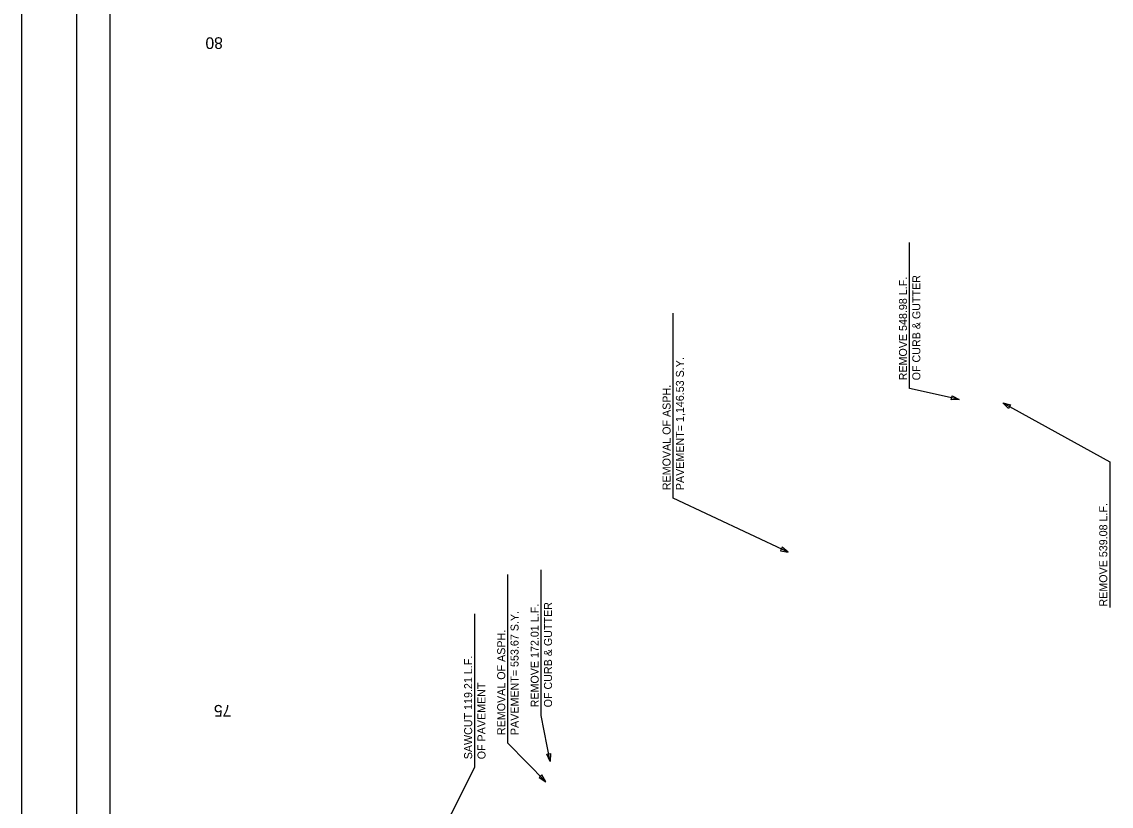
# Model space of a CAD drawing. Extents: x 2150645 to 2152288, y 141590 to 143592.
# Drawn here: x 2150645 to 2151462, y 142447 to 143034 of the extents above; entities that cross this region are included whole.
import ezdxf

# ---------------------------------------------------------------- set-up
doc = ezdxf.new("R2010")
doc.units = 0
for name, color, linetype in [('EX_Align', 7, 'Continuous'), ('EX_Align_Sta', 7, 'Continuous'), ('PR_Align_Ramp_D', 7, 'Continuous'), ('TOPO_DRAIN_Headwall', 7, 'Continuous'), ('TOPO_San Manhole', 7, 'Continuous')]:
    doc.layers.add(name, color=color, linetype=linetype)

msp = doc.modelspace()

# ---------------------------------------------------------------- linework, layer by layer
at = {"layer": 'EX_Align'}
msp.add_lwpolyline([(2150645.33, 141792.07), (2150645.33, 143592.07), (2151845.33, 143592.07), (2151845.33, 141792.07)], close=True, dxfattribs=at)
at = {"layer": 'PR_Align_Ramp_D'}
msp.add_lwpolyline([(2151761.58, 143546.45), (2151761.58, 141971.45), (2150711.58, 141971.45), (2150711.58, 143546.45)], close=True, dxfattribs=at)
at = {"layer": 'TOPO_DRAIN_Headwall'}
msp.add_lwpolyline([(2150686.58, 141873.95), (2150686.58, 143573.95), (2151786.58, 143573.95), (2151786.58, 141873.95)], close=True, dxfattribs=at)
at = {"layer": 'TOPO_San Manhole'}
for p, q in [((2151310.92, 142765.7), (2151310.92, 142868.89)), ((2151133.68, 142683.41), (2151133.68, 142816.16)), ((2151461.05, 142698.6), (2151461.05, 142595.42)), ((2151009.73, 142499.86), (2151009.73, 142620.17)), ((2151034.8, 142520.63), (2151034.8, 142623.82)), ((2150984.94, 142481.73), (2150984.94, 142590.81))]:
    msp.add_line(p, q, dxfattribs=at)
for points in [[(2151348.05, 142751.27), (2151310.92, 142759.7), (2151310.92, 142765.7)], [(2151380.69, 142748.77), (2151461.05, 142704.6), (2151461.05, 142698.6)], [(2151219.88, 142636.88), (2151133.68, 142677.41), (2151133.68, 142683.41)], [(2151041.43, 142480.06), (2151034.8, 142514.63), (2151034.8, 142520.63)], [(2151038.2, 142464.94), (2151009.73, 142493.86), (2151009.73, 142499.86)], [(2150932.15, 142371.03), (2150984.94, 142475.73), (2150984.94, 142481.73)]]:
    msp.add_lwpolyline(points, dxfattribs=at)
for points in [[(2151348.05, 142751.27), (2151342.06, 142751.14), (2151342.7, 142753.98)], [(2151380.69, 142748.77), (2151386.49, 142747.25), (2151385.09, 142744.7)], [(2151219.88, 142636.88), (2151215.23, 142640.68), (2151214, 142638.04)], [(2151041.43, 142480.06), (2151038.91, 142485.5), (2151041.77, 142486.05)], [(2151038.2, 142464.94), (2151035.16, 142470.11), (2151033.08, 142468.06)]]:
    msp.add_lwpolyline(points, close=True, dxfattribs=at)

# ---------------------------------------------------------------- texts
at = {"layer": 'EX_Align_Sta'}
for s, rotation, p in [('80', 180.34426, (2150796.02, 143022.83)), ('75', 180.50149, (2150802.32, 142522.51))]:
    msp.add_text(s, height=8.75, rotation=rotation, dxfattribs=at).set_placement(p)
at = {"layer": 'TOPO_San Manhole'}
for s, p in [('REMOVE 548.98 L.F.', (2151308.92, 142765.7)), ('OF CURB & GUTTER', (2151318.92, 142765.7)), ('PAVEMENT= 1,146.53 S.Y.', (2151141.68, 142683.41)), ('REMOVAL OF ASPH.', (2151131.68, 142683.41)), ('REMOVE 539.08 L.F.', (2151459.05, 142596.17)), ('REMOVE 172.01 L.F.', (2151032.8, 142520.63)), ('OF CURB & GUTTER', (2151042.8, 142520.63)), ('PAVEMENT= 553.67 S.Y.', (2151017.73, 142499.86)), ('REMOVAL OF ASPH.', (2151007.73, 142499.86)), ('SAWCUT 119.21 L.F. ', (2150982.94, 142481.73)), ('OF PAVEMENT', (2150992.94, 142481.73))]:
    msp.add_text(s, height=6, rotation=90, dxfattribs=at).set_placement(p)

doc.saveas('drawing.dxf')
